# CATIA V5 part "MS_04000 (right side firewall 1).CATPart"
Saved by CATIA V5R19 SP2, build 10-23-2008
Part number: MS_04002 (right side firewall 1)
Publications: "Face", "Arête"
Bounding box of the stored display mesh (mm): x -1431.36 to 13.468, y -333.51 to -114.626, z -114 to 174.022
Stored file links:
  D:\EPSA\GIT\ELIZ-2022\01 - Maquette CATIA\MS_Miscellanous_Finish_Assembly\MS_A0400 (Firewall)\MS_04000 (right side firewall 1).CATPart
  D:\EPSA\GIT\ELIZ-2022\01 - Maquette CATIA\MS_Miscellanous_Finish_Assembly\MS_A0400 (Firewall)\MS_A0400 (FireWall).CATProduct
  D:\EPSA\GIT\ELIZ-2022\01 - Maquette CATIA\FR_Frame_Body\FR_A0100 (frame)\Filaire.CATPart
  D:\EPSA\GIT\ELIZ-2022\01 - Maquette CATIA\MS_Miscellanous_Finish_Assembly\MS_A0400 (Firewall)\MS_04000 (test chape right side firewall).CATPart
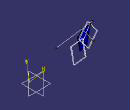
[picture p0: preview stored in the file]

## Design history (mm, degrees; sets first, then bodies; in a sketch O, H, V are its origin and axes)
Parameters
  `angle_pare-feu_lat` = 4.568 deg
SheetMetalParameters1: Thickness 1, BendRadius 1, KFactor 0.325257 {= log(min(100,max(20*SheetMetalParameters1.BendRadius,SheetMetalParameters1.Thickness)/SheetMetalParameters1.Thickness))/log(100)/2}, ReliefRadialLength 1, ReliefAxialLength 2, MinimumBendRadius 0
Set1
  DatumCurve1 to DatumCurve5: linked copy from another document
  Line1: linked copy from another document
Body1 (main body)
  Plane1: type 2Lines, Element1 DatumCurve1, Element2 DatumCurve2
  Plane2: type Offset, RefPlane Plane1, Offset 14
  Sketch1 on Plane2, origin (3.8523, -19.9899, -4.4703), H (-0.9819, -0.1892, 0), V (0.0406, -0.2106, 0.9767)
    line L1 (1416.0945, -106.0826) -> (1224.2187, 179.3837)
    line L2 (1086.9642, 122.5451) -> (1077.6265, -83.5435)
    line L3 (1224.2187, 179.3837) -> (1086.9642, 122.5451)
    line L4 (1077.6265, -83.5435) -> (1416.0945, -106.0826)
  Wall1: Thickness 1, Profile Sketch1
  d_NewWallOnEdge1: NewWallOnEdge_Edge edge [face of Wall1 | face of Wall1], NewWallOnEdge_Length 300, NewWallOnEdge_HeightLimitOffset 0, NewWallOnEdge_WidthOffset1 0, NewWallOnEdge_WidthOffset2 0, NewWallOnEdge_Angle 175.432 {= 180deg-`angle_pare-feu_lat`}, NewWallOnEdge_BendRadiusValue 1 {= SheetMetalParameters1.BendRadius}, NewWallOnEdge_BendTable SheetMetalParameters1, KFacteur 0.325257 {= log(min(100,max(20*d_NewWallOnEdge1.Radius,SheetMetalParameters1.Thickness)/SheetMetalParameters1.Thickness))/log(100)/2}
  Plane3: type Offset, RefPlane Plane1, Offset 15
  Sketch2 on face of d_NewWallOnEdge1, origin (12.4791, -106.4349, -18.0407), H (-0.9924, -0.1228, -0.001), V (0.0199, -0.1692, 0.9854)
    line L1 (1210.4094, 196.2058) -> (1400.425, 196.2058)
    line L2 (1400.425, 196.2058) -> (1217.6652, -113.4709)
    line L3 (1217.6652, -113.4709) -> (1219.7382, -116.8528)
    line L4 (1219.7382, -116.8528) -> (1657.2674, 142.855)
    line L5 (1657.2674, 142.855) -> (1503.3469, 393.9747)
    line L6 (1503.3469, 393.9747) -> (1212.7971, 221.5106)
    line L7 (1212.7971, 221.5106) -> (1210.4094, 196.2058)
    reference projected line E1 (1237.6901, -79.5398) -> (1392.5476, 182.858) from edge of DatumCurve3
    horizontal: L1 H
    parallelism: L5 L3, L6 L4
    coincidence: L2 E1
  Sketch3 on face of d_NewWallOnEdge1, origin (13.4676, -114.6262, -19.4493), H (-0.9932, -0.1167, 0), V (0.0194, -0.165, 0.9861)
    line L1 (1210.3812, 196.2225) -> (1400.3967, 196.2225)
    line L2 (1400.3967, 196.2225) -> (1217.4326, -113.3335)
    line L3 (1217.4326, -113.3335) -> (1219.5033, -116.7168)
    line L4 (1219.5033, -116.7168) -> (1657.2039, 142.7023)
    line L5 (1657.2039, 142.7023) -> (1503.4491, 393.9234)
    line L6 (1503.4491, 393.9234) -> (1212.7856, 221.6511)
    line L7 (1212.7856, 221.6511) -> (1210.3812, 196.2225)
    reference projected line E1 (1237.4798, -79.4157) -> (1392.5105, 182.8799) from edge of DatumCurve3
    horizontal: L1 H
    parallelism: L5 L3, L6 L4
    coincidence: L2 E1
  Pocket1: profile Sketch2, direction (0.1211, -0.9779, -0.1704), length 220
  Sketch4 on face of Wall1, origin (3.8523, -19.9899, -4.4703), H (0.9819, 0.1892, 0), V (0.0406, -0.2106, 0.9767)
    line L1 (-1327.8754, 43.683) -> (-1229.4854, -120.9456)
    line L2 (-1229.4854, -120.9456) -> (-1497.4945, -167.3352)
    line L3 (-1497.4945, -167.3352) -> (-1327.8754, 43.683)
    reference projected line E1 (-1248.0519, -89.8797) -> (-1401.3287, 166.5869) from edge of DatumCurve4
    coincidence: L1 E1
  Pocket2: profile Sketch4, direction (-0.1848, 0.9591, 0.2145), length 220
  Sketch5 on face of Wall1, origin (3.8523, -19.9899, -4.4703), H (0.9819, 0.1892, 0), V (0.0406, -0.2106, 0.9767)
    line L1 (-1324.6157, 41.7473) -> (-1231.5507, -106.027)
    line L2 (-1231.5507, -106.027) -> (-1272.9218, -119.4748)
    line L3 (-1272.9218, -119.4748) -> (-1377.1599, 24.0749)
    line L4 (-1377.1599, 24.0749) -> (-1324.6157, 41.7473)
  Pocket3: profile Sketch5, direction (-0.1848, 0.9591, 0.2145), length 220
  Sketch6 on face of d_NewWallOnEdge1, origin (12.5942, -107.4142, -18.2069), H (0.9924, 0.1228, 0.001), V (0.0199, -0.1692, 0.9854)
    line L1 (-1666.667, 178.3266) -> (-1746.5871, 74.912)
    line L2 (-1746.5871, 74.912) -> (-1399.619, -128.4113)
    line L3 (-1399.619, -128.4113) -> (-1322.4623, -28.5725)
    line L4 (-1322.4623, -28.5725) -> (-1666.667, 178.3266)
    parallelism: L3 L1
  Pocket4: profile Sketch6, direction (-0.1211, 0.9779, 0.1704), length 220
  Plane4: type 2Lines, Element1 DatumCurve5, Element2 Line1
  Plane5: type Offset, RefPlane Plane4, Offset 14, reversed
